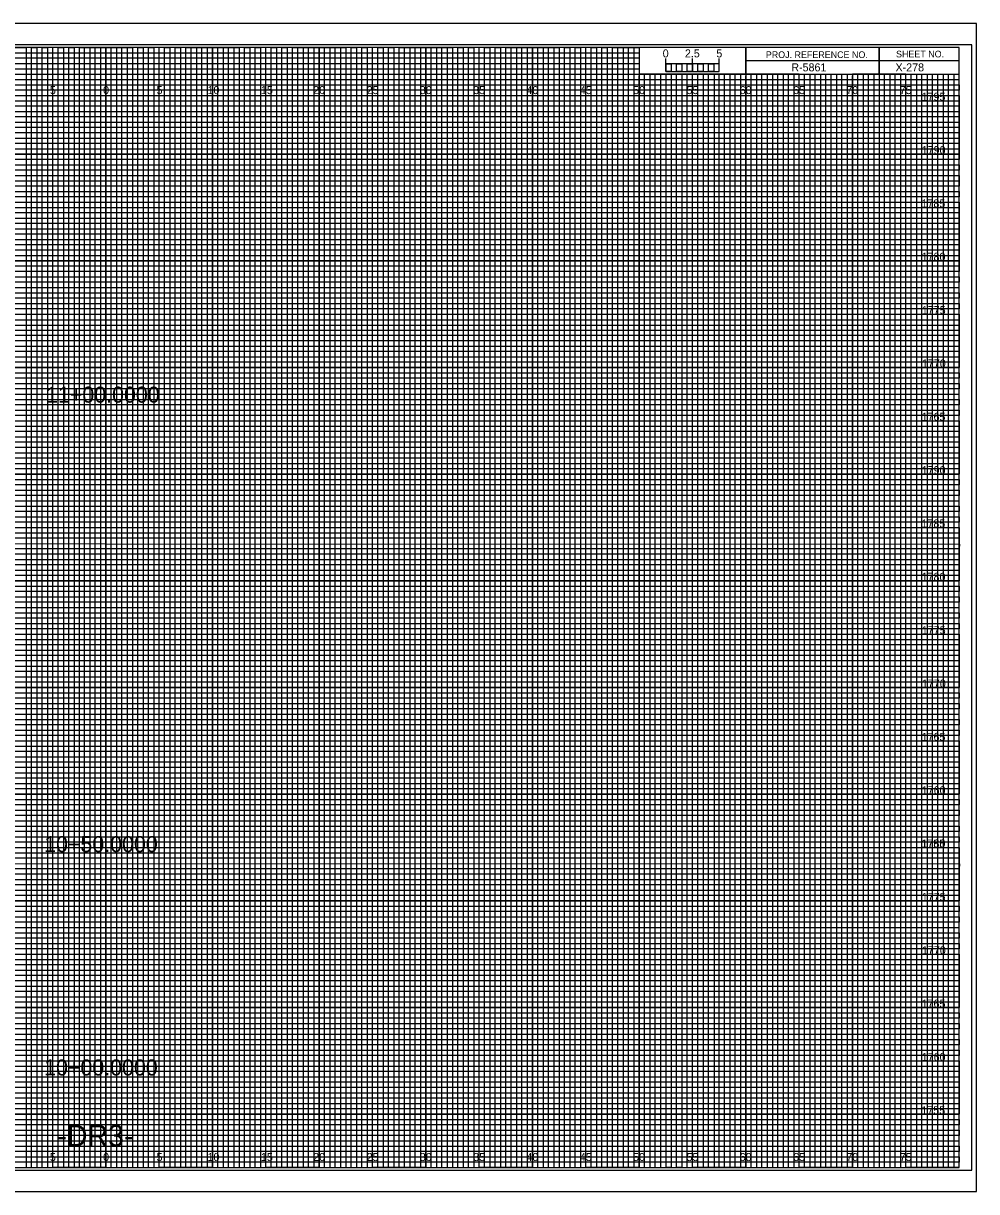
# Model space of a CAD drawing. Extents: x -7 to 162, y -2 to 217.
# Drawn here: x 72.2 to 161.7, y -2.3 to 107.3 of the extents above; entities that cross this region are included whole.
import ezdxf

# ---------------------------------------------------------------- set-up
doc = ezdxf.new("R2010")
doc.units = 0
for name, color, linetype in [('Prop Horizontal Alignment', 7, 'Continuous'), ('Prop XS Alignment Label', 7, 'Continuous'), ('Prop XS Bar Scale Labels', 7, 'Continuous'), ('Prop XS Project Number', 7, 'Continuous'), ('Prop XS Sheet Number', 7, 'Continuous'), ('Raster_Level_0', 7, 'Continuous'), ('Scratch_Level_3', 7, 'Continuous'), ('Sheet Cross Section CELL', 7, 'Continuous'), ('Sheet Cross Section Grid Major CELL', 7, 'Continuous'), ('Sheet Cross Section Grid Middle CELL', 7, 'Continuous'), ('Sheet Cross Section Grid Minor 1 CELL', 7, 'Continuous'), ('Sheet Cross Section Grid Minor 2 CELL', 7, 'Continuous'), ('Sheet Cross Section Scale CELL', 7, 'Continuous'), ('Sheet Cutting Line CELL', 7, 'Continuous'), ('Sheet DOT Grid CELL', 7, 'Continuous'), ('Sheet Plot Border Inside CELL', 7, 'Continuous'), ('Sheet Plot Border Outside CELL', 7, 'Continuous')]:
    doc.layers.add(name, color=color, linetype=linetype)

msp = doc.modelspace()

# ---------------------------------------------------------------- linework, layer by layer
at = {"layer": 'Sheet Cross Section CELL'}
for p, q in [((152.5, 105), (152.5, 102.5)), ((152.5, 102.5), (152.5, 105)), ((160, 103.75), (140, 103.75)), ((140, 103.75), (140, 102.5)), ((140, 102.5), (160, 102.5))]:
    msp.add_line(p, q, dxfattribs=at)
for points in [[(160, 105), (0, 105), (0, 0), (160, 0)], [(140, 105), (130, 105), (130, 102.52), (140, 102.52)], [(160, 105), (140, 105), (140, 102.5), (160, 102.5)]]:
    msp.add_lwpolyline(points, close=True, dxfattribs=at)
at = {"layer": 'Sheet Cross Section Grid Major CELL'}
for p, q in [((75, 105), (70, 105)), ((75, 0), (75, 105)), ((85, 105), (80, 105)), ((80, 105), (80, 0)), ((85, 0), (85, 105)), ((95, 105), (90, 105)), ((90, 105), (90, 0)), ((95, 0), (95, 105)), ((105, 105), (100, 105)), ((100, 105), (100, 0)), ((105, 0), (105, 105)), ((115, 105), (110, 105)), ((110, 105), (110, 0)), ((115, 0), (115, 105)), ((125, 105), (120, 105)), ((120, 105), (120, 0)), ((125, 0), (125, 105)), ((130, 105), (130, 0)), ((135, 0), (135, 102.5)), ((145, 102.5), (140, 102.5)), ((140, 102.5), (140, 0)), ((145, 0), (145, 102.5)), ((155, 102.5), (150, 102.5)), ((150, 102.5), (150, 0)), ((155, 0), (155, 102.5)), ((80, 0), (75, 0)), ((90, 0), (85, 0)), ((100, 0), (95, 0)), ((110, 0), (105, 0)), ((120, 0), (115, 0)), ((130, 0), (125, 0)), ((140, 0), (135, 0)), ((150, 0), (145, 0)), ((160, 0), (155, 0)), ((160, 0), (160, 0))]:
    msp.add_line(p, q, dxfattribs=at)
for points in [[(0, 100), (160, 100), (160, 95), (0, 95)], [(0, 90), (160, 90), (160, 85), (0, 85)], [(0, 80), (160, 80), (160, 75), (0, 75)], [(0, 70), (160, 70), (160, 65), (0, 65)], [(0, 60), (160, 60), (160, 55), (0, 55)], [(0, 50), (160, 50), (160, 45), (0, 45)], [(0, 40), (160, 40), (160, 35), (0, 35)], [(0, 30), (160, 30), (160, 25), (0, 25)], [(0, 20), (160, 20), (160, 15), (0, 15)], [(0, 10), (160, 10), (160, 5), (0, 5)]]:
    msp.add_lwpolyline(points, dxfattribs=at)
at = {"layer": 'Sheet Cross Section Grid Middle CELL'}
for points in [[(67.5, 105), (72.5, 105), (72.5, 0), (77.5, 0), (77.5, 105), (82.5, 105), (82.5, 0), (87.5, 0), (87.5, 105), (92.5, 105), (92.5, 0), (97.5, 0), (97.5, 105), (102.5, 105), (102.5, 0), (107.5, 0), (107.5, 105), (112.5, 105), (112.5, 0), (117.5, 0), (117.5, 105), (122.5, 105), (122.5, 0), (127.5, 0), (127.5, 105), (129.97, 105), (130, 105), (130, 102.5), (132.5, 102.5), (132.5, 0), (137.5, 0), (137.5, 102.5), (142.5, 102.5), (142.5, 0), (147.5, 0), (147.5, 102.5), (152.5, 102.5), (152.5, 0), (157.5, 0), (157.5, 102.5)], [(0, 102.5), (137.5, 102.5)], [(0, 92.5), (160, 92.5), (160, 97.5), (0, 97.5)], [(0, 82.5), (160, 82.5), (160, 87.5), (0, 87.5)], [(0, 72.5), (160, 72.5), (160, 77.5), (0, 77.5)], [(0, 62.5), (160, 62.5), (160, 67.5), (0, 67.5)], [(0, 52.5), (160, 52.5), (160, 57.5), (0, 57.5)], [(0, 42.5), (160, 42.5), (160, 47.5), (0, 47.5)], [(0, 32.5), (160, 32.5), (160, 37.5), (0, 37.5)], [(0, 22.5), (160, 22.5), (160, 27.5), (0, 27.5)], [(0, 12.5), (160, 12.5), (160, 17.5), (0, 17.5)], [(0, 2.5), (160, 2.5), (160, 7.5), (0, 7.5)]]:
    msp.add_lwpolyline(points, dxfattribs=at)
at = {"layer": 'Sheet Cross Section Grid Minor 1 CELL'}
for p, q in [((0, 104.5), (130, 104.5)), ((130, 104.5), (130, 103.99)), ((130, 103.99), (0, 103.99)), ((0, 103.5), (130, 103.5)), ((130, 102.95), (0, 102.95)), ((130, 103.5), (130, 102.95)), ((0, 102), (160, 102))]:
    msp.add_line(p, q, dxfattribs=at)
for points in [[(0, 101.5), (135, 101.5), (160, 101.5), (160, 101), (0, 101)], [(0, 100.5), (160, 100.5), (160, 99.5), (0, 99.5)], [(0, 99), (160, 99), (160, 98.5), (0, 98.49)], [(0, 98), (160, 98), (160, 97), (0, 97)], [(0, 96.5), (160, 96.5), (160, 96), (0, 96)], [(0, 95.5), (160, 95.5), (160, 94.5), (0, 94.5)], [(0, 94), (160, 94), (160, 93.5), (0, 93.5)], [(0, 93), (160, 93), (160, 92), (0, 92)], [(0, 91.5), (160, 91.5), (160, 91), (0, 91)], [(0, 90.5), (160, 90.5), (160, 89.5), (0, 89.5)], [(0, 89), (160, 89), (160, 88.5), (0, 88.5)], [(0, 88), (160, 88), (160, 86.98), (160, 86.5), (160, 86), (0, 86)], [(0, 87), (160, 87), (160, 86.5), (0, 86.5)], [(0, 85.5), (160, 85.5), (160, 84.5), (0, 84.52)], [(0, 84.52), (160, 84.5), (160, 84), (0, 84)], [(0, 83.5), (160, 83.5), (160, 83), (0, 83)], [(0, 82), (160, 82), (160, 81.5), (0, 81.5)], [(0, 81), (160, 81), (160, 80.5), (0, 80.5)], [(-0.04, 79.45), (160, 79.45), (160, 78.94), (-0.04, 78.94)], [(0, 78.5), (160, 78.5), (160, 78), (0, 78)], [(0, 77), (160, 77), (160, 76.5), (0, 76.5)], [(0, 76), (160, 76), (160, 75.5), (0, 75.5)], [(0, 74.5), (160, 74.5), (160, 74), (0, 74)], [(0, 73.5), (160, 73.5), (160, 73), (0, 73)], [(0, 72), (160, 72), (160, 71.5), (0, 71.5)], [(0, 71), (160, 71), (160, 70.5), (0, 70.5)], [(0, 69.5), (160, 69.5), (160, 68.99), (0, 69)], [(0, 68.5), (160, 68.5), (160, 68), (0, 68)], [(0, 67), (160, 67), (160, 66.5), (0, 66.5)], [(0, 66), (160, 66), (160, 65.5), (0, 65.5)], [(0, 64.5), (160, 64.5), (160, 64), (0, 64)], [(0, 63.5), (160, 63.5), (160, 63), (0, 63)], [(0, 62), (160, 62), (160, 61.5), (0, 61.5)], [(0, 61), (160, 61), (160, 60.5), (0, 60.5)], [(0, 59.5), (160, 59.5), (160, 59), (0, 59)], [(0, 58.5), (160.03, 58.45), (160, 58), (0, 58)], [(0, 57), (160, 57), (160, 56.5), (0, 56.5)], [(0, 56), (160, 56), (160, 55.5), (0, 55.5)], [(0, 54.5), (160, 54.5), (160, 54), (0, 54)], [(0, 53.5), (160, 53.5), (160, 53), (0, 53)], [(0, 52), (160, 52), (160, 51.5), (0, 51.5)], [(0, 51), (160, 51), (160, 50.5), (0, 50.5)], [(0, 49.5), (160, 49.5), (160, 49), (0, 49)], [(0, 48.5), (160, 48.5), (160, 48), (0, 48)], [(0, 47), (160, 47), (160, 46.5), (0, 46.5)], [(0, 46), (160, 46), (160, 45.5), (0, 45.5)], [(0, 44.5), (160, 44.5), (160, 44), (0, 44)], [(0, 43.5), (160, 43.5), (160, 43), (0, 43)], [(0, 42), (160, 42), (160, 41.5), (0, 41.5)], [(0, 41), (160, 41), (160, 40.5), (0, 40.5)], [(0, 39.5), (160, 39.5), (160, 38.99), (0, 39)], [(0, 38.5), (160, 38.5), (160, 38), (0, 38)], [(0, 37), (160, 37), (160, 36.5), (0, 36.5)], [(0, 36), (160, 36), (160, 35.5), (0, 35.5)], [(0, 34.5), (160, 34.5), (160, 34), (0, 34)], [(0, 33.5), (160, 33.5), (160, 33), (0, 33)], [(0, 32), (160, 32), (160, 31.5), (0, 31.5)], [(0, 31), (160, 31), (160, 30.5), (0, 30.5)], [(0, 29.5), (160, 29.5), (160, 29), (0, 29)], [(0, 28.5), (160.03, 28.46), (160, 28), (0, 28)], [(0, 27), (160, 27), (160, 26.5), (0, 26.5)], [(0, 26), (160, 26), (160, 25.5), (0, 25.5)], [(0, 24.5), (160, 24.5), (160, 24), (0, 24)], [(0, 23.5), (160, 23.5), (160, 23), (0, 23)], [(0, 22), (160, 22), (160, 21.5), (0, 21.5)], [(0, 21), (160, 21), (160, 20.5), (0, 20.5)], [(0, 19.5), (160, 19.5), (160, 19), (0, 19)], [(0, 18.5), (160, 18.5), (160, 18), (0, 18)], [(0, 17), (160, 17), (160, 16.5), (0, 16.5)], [(0, 16), (160, 16), (160, 15.5), (0, 15.5)], [(0, 14.5), (160, 14.5), (160, 14), (0, 14)], [(0, 13.5), (160, 13.5), (160, 13), (0, 13)], [(0, 12), (160, 12), (160, 11.5), (0, 11.5)], [(0, 11), (160, 11), (160, 10.5), (0, 10.5)], [(0, 9.5), (160, 9.5), (160, 9), (0, 9)], [(0, 8.5), (160, 8.5), (160, 8), (0, 8)], [(0, 7), (160, 7), (160, 6.5), (0, 6.5)], [(0, 6), (160, 6), (160, 5.5), (0, 5.5)], [(0, 4.5), (160, 4.5), (160, 4), (0, 4)], [(0, 3.5), (160, 3.5), (160, 3), (0, 3)], [(0, 2), (160, 2), (160, 1.5), (0, 1.5)], [(0, 1), (160, 1), (160, 0.5), (0, 0.5)]]:
    msp.add_lwpolyline(points, dxfattribs=at)
at = {"layer": 'Sheet Cross Section Grid Minor 2 CELL'}
for p, q in [((133.5, 102.5), (133, 102.5)), ((133, 102.5), (133, 0)), ((133.5, 0), (133.5, 102.5)), ((134.5, 102.5), (134, 102.5)), ((134, 102.5), (134, 0)), ((134.5, 0), (134.5, 102.5)), ((133, 0), (132.5, 0)), ((134, 0), (133.5, 0))]:
    msp.add_line(p, q, dxfattribs=at)
for points in [[(72.5, 0), (73, 0), (73, 105), (73.5, 105), (73.5, 0)], [(73.5, 0), (74, 0), (74, 105), (74.5, 105), (74.5, 0)], [(75, 0), (75.5, 0), (75.5, 105), (76, 105), (76, 0)], [(76, 0), (76.5, 0), (76.5, 105), (77, 105), (77, 0)], [(77.5, 0), (78, 0), (78, 105), (78.5, 105), (78.5, 0)], [(78.5, 0), (79, 0), (79, 105), (79.5, 105), (79.5, 0)], [(80, 0), (80.5, 0), (80.5, 105), (81, 105), (81, 0)], [(81, 0), (81.5, 0), (81.5, 105), (82, 105), (82, 0)], [(82.5, 0), (83, 0), (83, 105), (83.5, 105), (83.5, 0)], [(83.5, 0), (84, 0), (84, 105), (84.5, 105), (84.5, 0)], [(85, 0), (85.5, 0), (85.5, 105), (86, 105), (86, 0)], [(86, 0), (86.5, 0), (86.5, 105), (87, 105), (87, 0)], [(87.5, 0), (88, 0), (88, 105), (88.5, 105), (88.5, 0)], [(88.5, 0), (89, 0), (89, 105), (89.5, 105), (89.5, 0)], [(90, 0), (90.5, 0), (90.5, 105), (91, 105), (91, 0)], [(91, 0), (91.5, 0), (91.5, 105), (92, 105), (92, 0)], [(92.5, 0), (93, 0), (93, 105), (93.5, 105), (93.5, 0)], [(93.5, 0), (94, 0), (94, 105), (94.5, 105), (94.5, 0)], [(95, 0), (95.5, 0), (95.5, 105), (96, 105), (96, 0)], [(96, 0), (96.5, 0), (96.5, 105), (97, 105), (97, 0)], [(97.5, 0), (98, 0), (98, 105), (98.5, 105), (98.5, 0)], [(98.5, 0), (99, 0), (99, 105), (99.5, 105), (99.5, 0)], [(100, 0), (100.5, 0), (100.5, 105), (101, 105), (101, 0)], [(101, 0), (101.5, 0), (101.5, 105), (102, 105), (102, 0)], [(102.5, 0), (103, 0), (103, 105), (103.5, 105), (103.5, 0)], [(103.5, 0), (104, 0), (104, 105), (104.5, 105), (104.5, 0)], [(105, 0), (105.5, 0), (105.5, 105), (106, 105), (106, 0)], [(106, 0), (106.5, 0), (106.5, 105), (107, 105), (107, 0)], [(107.5, 0), (108, 0), (108, 105), (108.5, 105), (108.5, 0)], [(108.5, 0), (109, 0), (109, 105), (109.5, 105), (109.5, 0)], [(110, 0), (110.5, 0), (110.5, 105), (111, 105), (111, 0)], [(111, 0), (111.5, 0), (111.5, 105), (112, 105), (112, 0)], [(112.5, 0), (113, 0), (113, 105), (113.5, 105), (113.5, 0)], [(113.5, 0), (114, 0), (114, 105), (114.5, 105), (114.5, 0)], [(115, 0), (115.5, 0), (115.5, 105), (116, 105), (116, 0)], [(116, 0), (116.5, 0), (116.5, 105), (117, 105), (117, 0)], [(117.5, 0), (118, 0), (118, 105), (118.5, 105), (118.5, 0)], [(118.5, 0), (119, 0), (119, 105), (119.5, 105), (119.5, 0)], [(120, 0), (120.5, 0), (120.5, 105), (121, 105), (121, 0)], [(121, 0), (121.5, 0), (121.5, 105), (122, 105), (122, 0)], [(122.5, 0), (123, 0), (123, 105), (123.5, 105), (123.5, 0)], [(123.5, 0), (124, 0), (124, 105), (124.5, 105), (124.5, 0)], [(125, 0), (125.5, 0), (125.5, 105), (126, 105), (126, 0)], [(126, 0), (126.5, 0), (126.5, 105), (127, 105), (127, 0)], [(127.5, 0), (128, 0), (128, 105), (128.5, 105), (128.5, 0)], [(128.5, 0), (129, 0), (129, 105), (129.5, 105), (129.5, 0)], [(130, 0), (130.5, 0), (130.5, 102.5), (131.01, 102.5), (131.01, 0)], [(131, 0), (131.5, 0), (131.5, 102.5), (132, 102.5), (132, 0)], [(135, 0), (135.49, 0), (135.49, 102.5), (136, 102.5), (136, 0)], [(136, 0), (136.5, 0), (136.5, 102.5), (137.03, 102.5), (137.03, 0)], [(137.5, 0), (138, 0), (138, 102.5), (138.5, 102.5), (138.5, 0)], [(138.5, 0), (139, 0), (139, 102.5), (139.5, 102.5), (139.5, 0)], [(140, 0), (140.5, 0), (140.5, 102.5), (141, 102.5), (141, 0)], [(141, 0), (141.5, 0), (141.5, 102.5), (142, 102.5), (142, 0)], [(142.5, 0), (143, 0), (143, 102.5), (143.5, 102.5), (143.5, 0)], [(143.5, 0), (144, 0), (144, 102.5), (144.5, 102.5), (144.5, 0)], [(145, 0), (145.5, 0), (145.5, 102.5), (146, 102.5), (146, 0)], [(146, 0), (146.5, 0), (146.5, 102.5), (147, 102.5), (147, 0)], [(147.5, 0), (148, 0), (148, 102.5), (148.5, 102.5), (148.5, 0)], [(148.5, 0), (149, 0), (149, 102.5), (149.5, 102.5), (149.5, 0)], [(150, 0), (150.5, 0), (150.5, 102.5), (151, 102.5), (151, 0)], [(151, 0), (151.5, 0), (151.5, 102.5), (152, 102.5), (152, 0)], [(152.5, 0), (153, 0), (153, 102.5), (153.5, 102.5), (153.5, 0)], [(153.5, 0), (154, 0), (154, 102.5), (154.5, 102.5), (154.5, 0)], [(155, 0), (155.5, 0), (155.5, 102.5), (156, 102.5), (156, 0)], [(156, 0), (156.5, 0), (156.5, 102.5), (157, 102.5), (157, 0)], [(157.5, 0), (158, 0), (158, 102.5), (158.5, 102.5), (158.5, 0)], [(158.5, 0), (159, 0), (159, 102.5), (159.5, 102.5), (159.5, 0)]]:
    msp.add_lwpolyline(points, dxfattribs=at)
at = {"layer": 'Sheet Cross Section Scale CELL'}
for p, q in [((132.5, 102.75), (132.5, 103.95)), ((132.5, 103.45), (132.5, 103.95)), ((135, 102.75), (135, 103.95)), ((137.5, 102.75), (137.5, 103.95)), ((137.5, 103.45), (137.5, 103.95))]:
    msp.add_line(p, q, dxfattribs=at)
for points in [[(137.5, 103.45), (132.5, 103.45), (132.5, 102.75), (137.5, 102.75)], [(132.5, 103.45), (133, 103.45), (133, 102.75), (132.5, 102.75)], [(133.5, 103.45), (134, 103.45), (134, 102.75), (133.5, 102.75)], [(134.5, 103.45), (135, 103.45), (135, 102.75), (134.5, 102.75)], [(135.5, 103.45), (136, 103.45), (136, 102.75), (135.5, 102.75)], [(136.5, 103.45), (137, 103.45), (137, 102.75), (136.5, 102.75)]]:
    msp.add_lwpolyline(points, close=True, dxfattribs=at)
at = {"layer": 'Sheet Cutting Line CELL'}
for p, q in [((161.65, 107.25), (-6.7, 107.25)), ((-6.7, -2.25), (161.65, -2.25))]:
    msp.add_line(p, q, dxfattribs=at)
at = {"layer": 'Sheet DOT Grid CELL'}
for p, q in [((75, 0), (75, 105)), ((80, 0), (80, 105)), ((85, 0), (85, 105)), ((90, 0), (90, 105)), ((95, 0), (95, 105)), ((100, 0), (100, 105)), ((105, 0), (105, 105)), ((110, 0), (110, 105)), ((115, 0), (115, 105)), ((120, 0), (120, 105)), ((125, 0), (125, 105)), ((130, 0), (130, 102.34)), ((135, 0), (135, 102.34)), ((140, 0), (140, 102.34)), ((145, 0), (145, 102.34)), ((150, 0), (150, 102.34)), ((155, 0), (155, 102.34)), ((0, 100), (160, 100)), ((0, 95), (160, 95)), ((0, 90), (160, 90)), ((0, 85), (160, 85)), ((0, 80), (160, 80)), ((0, 75), (160, 75)), ((0, 70), (160, 70)), ((0, 65), (160, 65)), ((0, 60), (160, 60)), ((0, 55), (160, 55)), ((0, 50), (160, 50)), ((0, 45), (160, 45)), ((0, 40), (160, 40)), ((0, 35), (160, 35)), ((0, 30), (160, 30)), ((0, 25), (160, 25)), ((0, 20), (160, 20)), ((0, 15), (160, 15)), ((0, 10), (160, 10)), ((0, 5), (160, 5))]:
    msp.add_line(p, q, dxfattribs=at)
at = {"layer": 'Sheet Plot Border Inside CELL'}
msp.add_lwpolyline([(-5.4, -0.25), (161.2, -0.25), (161.2, 105.25), (-5.4, 105.25)], close=True, dxfattribs=at)
at = {"layer": 'Sheet Plot Border Outside CELL'}
msp.add_lwpolyline([(-6.7, -2.25), (161.65, -2.25), (161.65, 107.25), (-6.7, 107.25)], close=True, dxfattribs=at)

# ---------------------------------------------------------------- texts
at = {"layer": 'Prop Horizontal Alignment'}
for s, p in [('11+00.0000', (74.38, 71.7)), ('10+50.0000', (74.2, 29.57)), ('10+00.0000', (74.2, 8.64))]:
    msp.add_text(s, height=1.5, dxfattribs=at).set_placement(p)
at = {"layer": 'Prop XS Alignment Label'}
msp.add_text('-DR3-', height=2, dxfattribs=at).set_placement((75.44, 2))
at = {"layer": 'Prop XS Bar Scale Labels'}
for s, p in [('2.5', (134.29, 104.06)), ('5', (137.24, 104.06))]:
    msp.add_text(s, height=0.75, dxfattribs=at).set_placement(p)
at = {"layer": 'Prop XS Project Number'}
msp.add_text('R-5861', height=0.75, dxfattribs=at).set_placement((144.27, 102.75))
at = {"layer": 'Prop XS Sheet Number'}
msp.add_text('X-278', height=0.75, dxfattribs=at).set_placement((154.04, 102.75))
at = {"layer": 'Raster_Level_0'}
for s, p in [('5', (74.74, 100.62)), ('0', (79.73, 100.62)), ('0', (79.73, 100.62)), ('5', (84.74, 100.62)), ('10', (89.52, 100.62)), ('15', (94.53, 100.62)), ('20', (99.43, 100.62)), ('25', (104.44, 100.62)), ('30', (109.43, 100.62)), ('35', (114.44, 100.62)), ('40', (119.43, 100.62)), ('45', (124.44, 100.62)), ('50', (129.43, 100.62)), ('55', (134.44, 100.62)), ('60', (139.43, 100.62)), ('65', (144.44, 100.62)), ('70', (149.43, 100.62)), ('75', (154.44, 100.62)), ('5', (74.74, 0.62)), ('0', (79.73, 0.62)), ('0', (79.73, 0.62)), ('5', (84.74, 0.62)), ('10', (89.52, 0.62)), ('15', (94.53, 0.62)), ('20', (99.43, 0.62)), ('25', (104.44, 0.62)), ('30', (109.43, 0.62)), ('35', (114.44, 0.62)), ('40', (119.43, 0.62)), ('45', (124.44, 0.62)), ('50', (129.43, 0.62)), ('55', (134.44, 0.62)), ('60', (139.43, 0.62)), ('65', (144.44, 0.62)), ('70', (149.43, 0.62)), ('75', (154.44, 0.62))]:
    msp.add_text(s, height=0.75, dxfattribs=at).set_placement(p)
at = {"layer": 'Scratch_Level_3'}
for s, p in [('1795', (156.49, 100)), ('1790', (156.5, 95)), ('1785', (156.48, 90)), ('1780', (156.49, 85)), ('1775', (156.51, 80)), ('1770', (156.52, 75)), ('1765', (156.49, 70)), ('1790', (156.5, 65)), ('1785', (156.48, 60)), ('1780', (156.49, 55)), ('1775', (156.51, 50)), ('1770', (156.52, 45)), ('1765', (156.49, 40)), ('1760', (156.5, 35)), ('1755', (156.47, 30)), ('1780', (156.49, 30)), ('1775', (156.51, 25)), ('1770', (156.52, 20)), ('1765', (156.49, 15)), ('1760', (156.5, 10)), ('1755', (156.47, 5))]:
    msp.add_text(s, height=0.75, dxfattribs=at).set_placement(p)
at = {"layer": 'Sheet Cross Section CELL'}
for s, p in [('PROJ. REFERENCE NO.', (141.88, 104)), ('SHEET NO.', (154.09, 104.06))]:
    msp.add_text(s, height=0.625, dxfattribs=at).set_placement(p)
at = {"layer": 'Sheet Cross Section Scale CELL'}
msp.add_text('0', height=0.75, dxfattribs=at).set_placement((132.21, 104.06))

doc.saveas('drawing.dxf')
